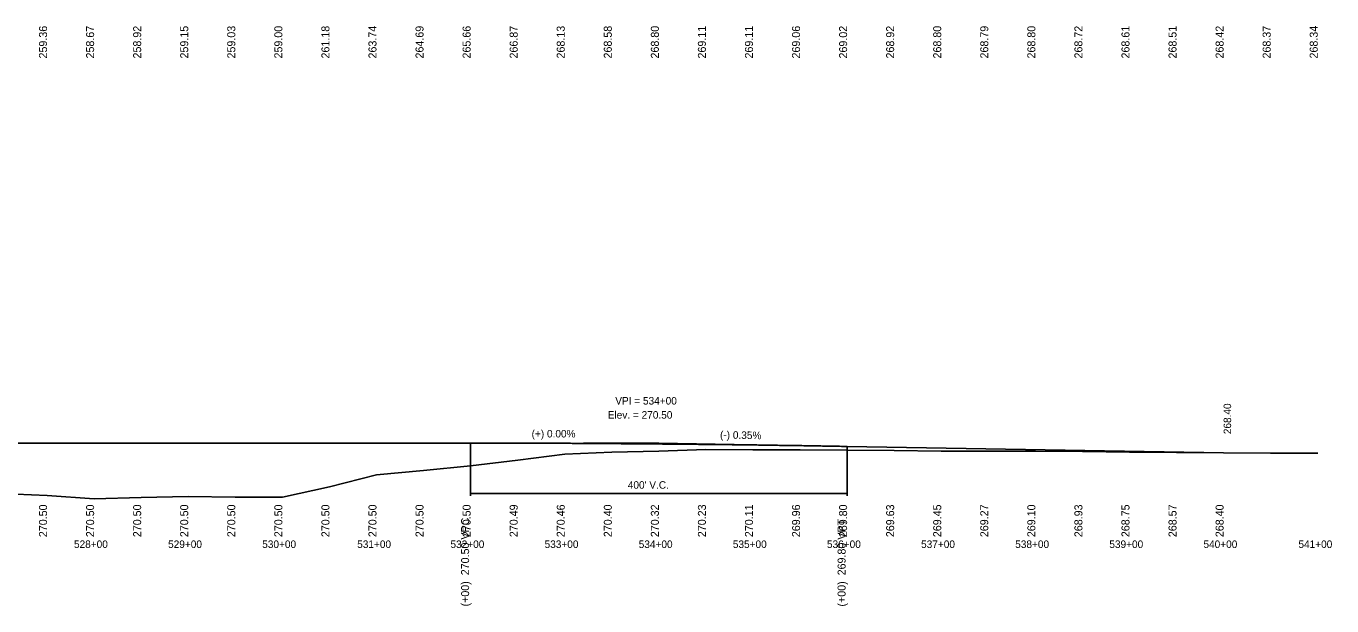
# Model space of a CAD drawing. Extents: x 49241 to 62599, y 49216 to 56011.
# Drawn here: x 61212 to 62599, y 53687 to 54304 of the extents above; entities that cross this region are included whole.
import ezdxf

# ---------------------------------------------------------------- set-up
doc = ezdxf.new("R2010")
doc.units = 0
for name, color, linetype in [('Level 40', 7, 'Continuous'), ('Level 41', 7, 'Continuous'), ('Level 42', 7, 'Continuous'), ('Level 43', 7, 'Continuous'), ('Level 45', 7, 'Continuous')]:
    doc.layers.add(name, color=color, linetype=linetype)

msp = doc.modelspace()

# ---------------------------------------------------------------- linework, layer by layer
at = {"layer": 'Level 40'}
for points in [[(61184.2, 53806.6), (61234.2, 53804.6), (61284.2, 53801.2), (61334.2, 53802.4), (61384.2, 53803.6), (61434.2, 53802.9), (61484.2, 53802.8), (61534.2, 53813.7), (61584.2, 53826.5), (61634.2, 53831.3), (61684.2, 53836.1), (61734.2, 53842.1), (61784.2, 53848.4), (61834.2, 53850.7), (61884.2, 53851.8), (61934.2, 53853.4), (61984.2, 53853.3), (62034.2, 53853.1), (62084.2, 53852.9), (62134.2, 53852.4), (62184.2, 53851.8)], [(62184.2, 53851.8), (62234.2, 53851.8), (62284.2, 53851.8), (62334.2, 53851.4), (62384.2, 53850.8), (62434.2, 53850.3), (62484.2, 53849.9), (62534.2, 53849.7), (62584.2, 53849.5)]]:
    msp.add_lwpolyline(points, dxfattribs=at)
at = {"layer": 'Level 41'}
for p, q in [((61684.2, 53804.3), (61684.2, 53860.3)), ((61804.2, 53860.3), (61884.2, 53860.3)), ((61964.1, 53858.9), (61884.2, 53860.3)), ((62084.2, 53804.3), (62084.2, 53856.8)), ((61684.2, 53806.8), (62084.2, 53806.8))]:
    msp.add_line(p, q, dxfattribs=at)
at = {"layer": 'Level 45'}
for p, q in [((58984.2, 53860.3), (61684.2, 53860.3)), ((62084.2, 53856.8), (62484.2, 53849.8))]:
    msp.add_line(p, q, dxfattribs=at)
msp.add_spline([(61684.2, 53860.3), (61692.2, 53860.3), (61700.2, 53860.3), (61708.2, 53860.3), (61716.2, 53860.3), (61724.2, 53860.3), (61732.2, 53860.2), (61740.2, 53860.2), (61748.2, 53860.2), (61756.2, 53860.2), (61764.2, 53860.2), (61772.2, 53860.1), (61780.2, 53860.1), (61788.2, 53860.1), (61796.2, 53860), (61804.2, 53860), (61812.2, 53859.9), (61820.2, 53859.9), (61828.2, 53859.8), (61836.2, 53859.8), (61844.2, 53859.7), (61852.2, 53859.7), (61860.2, 53859.6), (61868.2, 53859.5), (61876.2, 53859.5), (61884.2, 53859.4), (61892.2, 53859.3), (61900.2, 53859.3), (61908.2, 53859.2), (61916.2, 53859.1), (61924.2, 53859), (61932.2, 53858.9), (61940.2, 53858.9), (61948.2, 53858.8), (61956.2, 53858.7), (61964.2, 53858.6), (61972.2, 53858.5), (61980.2, 53858.4), (61988.2, 53858.3), (61996.2, 53858.2), (62004.2, 53858.1), (62012.2, 53857.9), (62020.2, 53857.8), (62028.2, 53857.7), (62036.2, 53857.6), (62044.2, 53857.5), (62052.2, 53857.3), (62060.2, 53857.2), (62068.2, 53857.1), (62076.2, 53856.9), (62084.2, 53856.8)], degree=3, dxfattribs=at)

# ---------------------------------------------------------------- texts
at = {"layer": 'Level 41'}
for s, p in [('VPI = 534+00', (61837.9, 53901.3)), ('Elev. = 270.50', (61829.9, 53886.3)), ('(+) 0.00%', (61749, 53866.3)), ("400' V.C.", (61851.2, 53811.8))]:
    msp.add_text(s, height=8, dxfattribs=at).set_placement(p)
for s, height, rotation, p in [('268.40', 8, 90, (62492.2, 53869.8)), ('(-) 0.35%', 8, 358.9974, (61949.1, 53865.2)), ('(+00)  270.50 VPC', 8.5, 90, (61682.6, 53686.6)), ('(+00)  269.80 VPT', 8.5, 90, (62082.6, 53686.5))]:
    msp.add_text(s, height=height, rotation=rotation, dxfattribs=at).set_placement(p)
at = {"layer": 'Level 42'}
for s, p in [('528+00', (61262.8, 53748.8)), ('529+00', (61362.8, 53748.8)), ('530+00', (61462.8, 53748.8)), ('531+00', (61563.7, 53748.8)), ('532+00', (61662.8, 53748.8)), ('533+00', (61762.8, 53748.8)), ('534+00', (61862.8, 53748.8)), ('535+00', (61962.8, 53748.8)), ('536+00', (62062.8, 53748.8)), ('537+00', (62162.8, 53748.8)), ('538+00', (62262.8, 53748.8)), ('539+00', (62362.8, 53748.8)), ('540+00', (62462.8, 53748.8)), ('541+00', (62563.7, 53748.8))]:
    msp.add_text(s, height=8, dxfattribs=at).set_placement(p)
at = {"layer": 'Level 43'}
for s, p in [('259.36', (61234.2, 54269.3)), ('258.67', (61284.2, 54269.3)), ('258.92', (61334.2, 54269.3)), ('259.15', (61384.2, 54269.3)), ('259.03', (61434.2, 54269.3)), ('259.00', (61484.2, 54269.3)), ('261.18', (61534.2, 54269.3)), ('263.74', (61584.2, 54269.3)), ('264.69', (61634.2, 54269.3)), ('265.66', (61684.2, 54269.3)), ('266.87', (61734.2, 54269.3)), ('268.13', (61784.2, 54269.3)), ('268.58', (61834.2, 54269.3)), ('268.80', (61884.2, 54269.3)), ('269.11', (61934.2, 54269.3)), ('269.11', (61984.2, 54269.3)), ('269.06', (62034.2, 54269.3)), ('269.02', (62084.2, 54269.3)), ('268.92', (62134.2, 54269.3)), ('268.80', (62184.2, 54269.3)), ('268.79', (62234.2, 54269.3)), ('268.80', (62284.2, 54269.3)), ('268.72', (62334.2, 54269.3)), ('268.61', (62384.2, 54269.3)), ('268.51', (62434.2, 54269.3)), ('268.42', (62484.2, 54269.3)), ('268.37', (62534.2, 54269.3)), ('268.34', (62584.2, 54269.3)), ('270.50', (61234.2, 53760.3)), ('270.50', (61284.2, 53760.3)), ('270.50', (61334.2, 53760.3)), ('270.50', (61384.2, 53760.3)), ('270.50', (61434.2, 53760.3)), ('270.50', (61484.2, 53760.3)), ('270.50', (61534.2, 53760.3)), ('270.50', (61584.2, 53760.3)), ('270.50', (61634.2, 53760.3)), ('270.50', (61684.2, 53760.3)), ('270.49', (61734.2, 53760.3)), ('270.46', (61784.2, 53760.3)), ('270.40', (61834.2, 53760.3)), ('270.32', (61884.2, 53760.3)), ('270.23', (61934.2, 53760.3)), ('270.11', (61984.2, 53760.3)), ('269.96', (62034.2, 53760.3)), ('269.80', (62084.2, 53760.3)), ('269.63', (62134.2, 53760.3)), ('269.45', (62184.2, 53760.3)), ('269.27', (62234.2, 53760.3)), ('269.10', (62284.2, 53760.3)), ('268.93', (62334.2, 53760.3)), ('268.75', (62384.2, 53760.3)), ('268.57', (62434.2, 53760.3)), ('268.40', (62484.2, 53760.3))]:
    msp.add_text(s, height=8.5, rotation=90, dxfattribs=at).set_placement(p)

doc.saveas('drawing.dxf')
